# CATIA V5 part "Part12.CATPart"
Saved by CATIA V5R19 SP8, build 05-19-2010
Part number: Plaque
Bounding box of the stored display mesh (mm): x 0 to 12, y 748.765 to 1543.324, z -188.848 to 607.563
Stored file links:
  G:\EU_thinkMotion\CFAO_2010\MMS_groupe1\MMS_groupe1\OK\ppiault\piault\piault_cfao\Part12.CATPart
  D:\Catia\Finaltest.CATProduct
  G:\Catia Projet\CFAO2\Product2.CATProduct
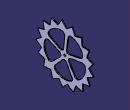
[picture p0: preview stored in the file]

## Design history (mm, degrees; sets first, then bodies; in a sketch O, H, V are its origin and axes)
Parameters
  rayon_int_rab = 328 mm
  rayon_ext_rab = 400 mm
External parameters (linked from other documents)
  External.DiametreRabatteur = 400 mm
  External.Epaisseur = 5 mm
Body1 (main body)
  Sketch1 on yz-plane, origin (0, 0, 0), H (0, 1, 0), V (0, 0, 1)
    arc A1 centre (1148.6766, 210.1337) radius 328 from (1476.6213, 216.1551) to (1457.2481, 98.9239) ccw
    point P1 (1148.6766, 210.1337)
    point P2 (971.7064, -68.7052)
    point P3 (875.9444, 22.3008)
    line L1 (1476.6213, 216.1551) -> (1543.324, 144.9157)
    point P5 (1543.324, 144.9157)
    line L2 (1543.324, 144.9157) -> (1457.2481, 98.9239)
    circle A2 centre (1148.6766, 210.1337) radius 15
    radius A1 = 328 {= 0.82*External.DiametreRabatteur}
    distance P1 P5 = 400 {= External.DiametreRabatteur}
    angle L1 L2 = 75
    radius A2 = 15
  Pad1: profile Sketch1, direction (1, 0, 0), length 12 {= 2.4*External.Epaisseur}
  CircPattern1: of Pad1, instances 18, angular step 21.1765, axis from end face of Pad1
  Sketch2 on face of CircPattern1, origin (12, 0, 0), H (0, 1, 0), V (0, 0, 1)
    point P1 (1204.7983, 280.4924)
    point P2 (1204.7983, 280.4924)
    arc A1 centre (1204.7983, 280.4924) radius 35 from (1170.2169, 285.8891) to (1212.3122, 246.3085) ccw
    point P3 (1212.3122, 246.3085)
    point P4 (1170.2169, 285.8891)
    arc A2 centre (1230.2398, 443.5192) radius 35 from (1235.6365, 478.1006) to (1195.6584, 448.9159) ccw
    line L1 (1170.2169, 285.8891) -> (1195.6584, 448.9159)
    point P5 (1212.3122, 246.3085)
    line L2 (1212.3122, 246.3085) -> (1364.0541, 279.6626)
    point P6 (1170.2169, 285.8891)
    arc A3 centre (1354.1869, 324.5529) radius 45.9619 from (1364.0541, 279.6626) to (1400.1351, 323.429) ccw
    arc A4 centre (1204.7983, 280.4924) radius 200 from (1400.1351, 323.429) to (1235.6365, 478.1006) ccw
    reference projected point E1 (1148.6766, 210.1337) from axis of face of CircPattern1
    reference projected point E2 (1148.6766, 210.1337) from axis of face of CircPattern1
    distance E1 P2 = 90 {= 90/400*External.DiametreRabatteur}
    distance E2 A4 = 290 {= 290/400*External.DiametreRabatteur}
    coincidence: P2 P1, P3 A1, P4 A1, L2 P5, L1 P6, P6 P4, P5 P3
    tangency: L1 A2, A1 L1, A3 L2
  Pocket1: profile Sketch2, direction (-1, 0, 0), length 12 {= 2.4*External.Epaisseur}
  CircPattern2: of Pocket1, instances 6, angular step 72, axis from face of CircPattern1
